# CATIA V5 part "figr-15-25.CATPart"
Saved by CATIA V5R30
Part number: Part1
Bounding box of the stored display mesh (mm): x -50 to 50, y -25 to 26, z -24 to 1
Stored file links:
  D:\PROJECTS\CATIA V56R 2020\Resources\Parts File\c15_catia_v5_6r2020_prt\figr-15-25.CATPart
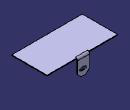
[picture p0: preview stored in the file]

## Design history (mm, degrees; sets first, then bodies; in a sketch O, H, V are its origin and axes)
SheetMetalParameters1: Thickness 1, BendRadius 2, KFactor 0.400515 {= log(min(100,max(20*SheetMetalParameters1.BendRadius,SheetMetalParameters1.Thickness)/SheetMetalParameters1.Thickness))/log(100)/2}, ReliefRadialLength 1, ReliefAxialLength 2, MinimumBendRadius 0
Body1 (main body)
  Sketch1 on xy-plane, origin (0, 0, 0), H (1, 0, 0), V (0, 1, 0)
    line L1 (-50, 25) -> (50, 25)
    line L2 (50, 25) -> (50, -25)
    line L3 (50, -25) -> (-50, -25)
    line L4 (-50, -25) -> (-50, 25)
    length L1 = 100
    distance V L2 = 50
    length L2 = 50
    distance H L3 = 25
    horizontal: L1 H, L3 H
    vertical: L2 V, L4 V
  Wall1: Thickness 1, Profile Sketch1
  Sketch2 on face of Wall1, origin (50, 25, 0), H (-1, 0, 0), V (0, 0, 1)
    line L1 (42.3549, 1) -> (42.3549, -19)
    point P2 (42.3549, -19)
    line L2 (42.3549, -19) -> (47.3549, -24)
    point P3 (47.3549, -24)
    line L3 (47.3549, -24) -> (54.3549, -24)
    point P4 (54.3549, -24)
    line L4 (54.3549, -24) -> (59.3549, -19)
    point P5 (59.3549, -19)
    line L5 (59.3549, -19) -> (59.3549, 1)
    line L6 (59.3549, 1) -> (42.3549, 1)
    reference projected line E1 (100, 1) -> (0, 1) from edge [face of Wall1 | face of Wall1]
    ellipse A1 centre (50.1164, -15.2153) semi-axes 5.0583, 2.1402 rotation 0
    length L5 = 20
    length L1 = 20
    length L3 = 7
    distance P4 L5 = 5
    distance P2 P3 H = 5
    distance L3 P5 = 5
    vertical: L1 V, L5 V
    horizontal: L3 H, L6 H
    coincidence: L6 E1
    parallelism: A1 L3
  d_NewWallOnEdge1: NewWallOnEdge_Edge edge [face of Wall1 | face of Wall1], NewWallOnEdge_WallProfile Sketch2, NewWallOnEdge_Length 100, NewWallOnEdge_HeightLimitOffset 0, NewWallOnEdge_WidthOffset1 0, NewWallOnEdge_WidthOffset2 0, NewWallOnEdge_Angle 0, NewWallOnEdge_BendRadiusValue 2 {= SheetMetalParameters1.BendRadius}, NewWallOnEdge_BendTable SheetMetalParameters1, KFacteur 0.400515 {= log(min(100,max(20*d_NewWallOnEdge1.Radius,SheetMetalParameters1.Thickness)/SheetMetalParameters1.Thickness))/log(100)/2}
